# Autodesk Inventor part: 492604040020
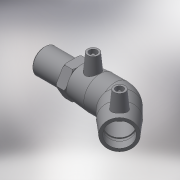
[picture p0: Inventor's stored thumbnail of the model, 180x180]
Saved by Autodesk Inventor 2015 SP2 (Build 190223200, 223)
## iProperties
Created: 2017-06
Part Number: 492604040020
Material: Generic
Description: PLASSON 45° ELBOW TRANSITION MALE 40-2"
Document SubType Name: Modeling
Designer: KIM
Mass: 232.924 g
Surface Area: 540.109 cm^2
Volume: 232.924 cm^3
Density: 1 g/cm^3
Appearance: Default
Author: KIM
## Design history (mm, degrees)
derived "492604.ipt"
feature "Solid1::492604.ipt"
tag "TaggingFeature1"
body "Solid1"
other parameters: "d2" = 56, "d4" = 27, "d5" = 50.4, "d8" = 168 deg, "d10" = 17.6, "d11" = 5.86667, "d29" = 47, "d30" = 15, "d31" = 37.8, "d34" = 5 deg, "d41" = 4, "d42" = 14, "d43" = 0, "d50" = 26, "d51" = 17.6, "d52" = 45.32, "d54" = 135 deg, "d86" = 25.2, "d87" = 135 deg, "d88" = 108, "d90" = 44, "d91" = 0, "d92" = 44, "d93" = 0, "d101" = 3, "d102" = 0, "d107" = 0.1, "d108" = 29, "d109" = 59.614, "d110" = 41, "d111" = 10.25, "d112" = 72.8, "d113" = 41.7298, "d114" = 36.9, "d116" = 1.68, "d122" = 0, "d123" = 2.9807, "L_" = 149, "L_1" = 44, "D_" = 29, "A_" = 47, "d_2" = 12, "L_2" = 41, "R_" = 59.614, "D_1" = 56
